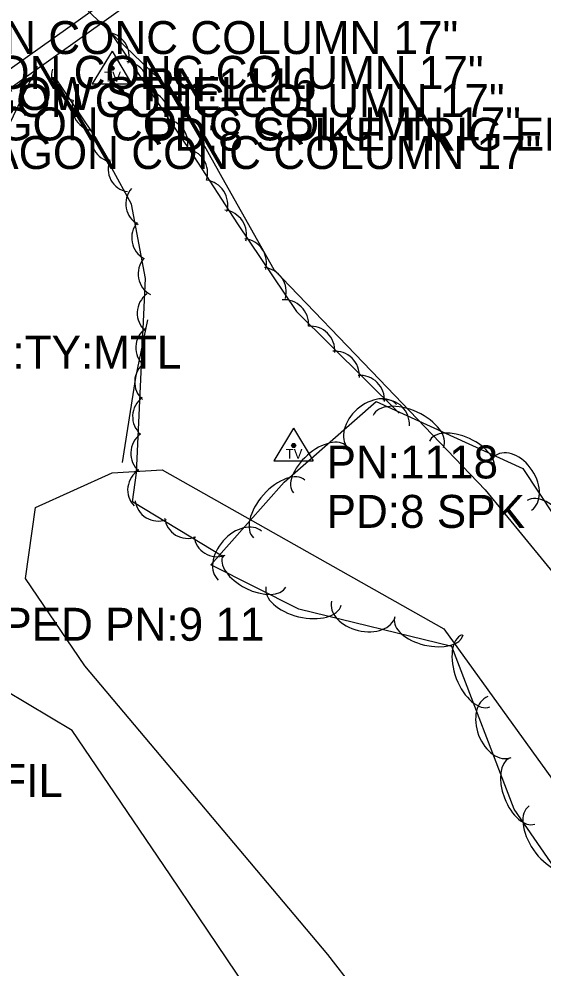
# Model space of a CAD drawing. Extents: x 1451369 to 1458940, y 1868647 to 1875095.
# Drawn here: x 1454278.5 to 1454358, y 1871314.6 to 1871458.6 of the extents above; entities that cross this region are included whole.
import ezdxf

# ---------------------------------------------------------------- set-up
doc = ezdxf.new("R2010")
doc.units = 0
for name, color, linetype in [('E_Existing_ROW', 7, 'Continuous'), ('E_Quarter Section Line', 7, 'Continuous'), ('E_ROW Point Number', 7, 'Continuous'), ('E_Station Offset', 7, 'Continuous'), ('E_Tract Residual', 7, 'Continuous'), ('S_EXIST_ROW', 7, 'Continuous'), ('S_MISC_BOUNDARY', 7, 'Continuous'), ('S_MISC_STRUCTURES_ANNOT', 7, 'Continuous'), ('S_PARKING', 7, 'Continuous'), ('S_PRIMARY_CTL_ANNOT', 7, 'Continuous'), ('S_SECONDARY_CTL_ANNOT', 7, 'Continuous'), ('S_SIDE_DRAIN_ANNOT', 7, 'Continuous'), ('S_SURVEY_TEXT_ANNOT', 7, 'Continuous')]:
    doc.layers.add(name, color=color, linetype=linetype)

msp = doc.modelspace()

# ---------------------------------------------------------------- linework, layer by layer
at = {"layer": 'E_Existing_ROW'}
msp.add_line((1454227.64, 1871415.7), (1454553.13, 1871647.85), dxfattribs=at)
at = {"layer": 'E_Quarter Section Line'}
msp.add_line((1454551.64, 1871643.91), (1454234.22, 1871417.39), dxfattribs=at)
at = {"layer": 'E_ROW Point Number'}
for points in [[(1454292.27, 1871456.79), (1454305.07, 1871437.72), (1454311.68, 1871427.52), (1454320.66, 1871414.23), (1454336.23, 1871398.78)], [(1454309.62, 1871376.9), (1454295.77, 1871385.31), (1454296.35, 1871389.74), (1454297.71, 1871419.2), (1454295.61, 1871430.5), (1454289.64, 1871441.43), (1454283.98, 1871449.8)], [(1454377.48, 1871304.11), (1454353.64, 1871338.7), (1454344.21, 1871363.37), (1454320.99, 1871369.01), (1454307.64, 1871375.76), (1454318.78, 1871388.29), (1454332.74, 1871400.56), (1454354.98, 1871390.38), (1454371.8, 1871364.92)]]:
    msp.add_lwpolyline(points, dxfattribs=at)
for centre, major_axis, ratio, start_param, end_param in [((1454291.71, 1871453.01), (-2.03, 3.02), 0.965975, 3.824523, 5.597723), ((1454294.63, 1871448.55), (-2.03, 3.02), 0.965975, 3.824523, 5.597723), ((1454287.1, 1871449.93), (2.04, -3.02), 0.99929, 3.825789, 5.598989), ((1454297.63, 1871444.2), (-2.03, 3.02), 0.965975, 3.824523, 5.597723), ((1454290.24, 1871445.23), (2.04, -3.02), 0.99929, 3.825789, 5.598989), ((1454300.61, 1871439.82), (-2.03, 3.02), 0.965975, 3.824523, 5.597723), ((1454293.15, 1871440.47), (-2.69, -2.46), 0.973191, 5.162702, 6.935903), ((1454303.6, 1871435.32), (-1.98, 3.06), 0.965979, 3.825789, 5.598989), ((1454295.66, 1871435.95), (-2.69, -2.46), 0.973191, 5.162702, 6.935903), ((1454306.65, 1871430.56), (-1.98, 3.06), 0.965979, 3.825789, 5.598989), ((1454298.35, 1871430.63), (-2.7, -2.45), 0.978082, 4.853565, 6.626766), ((1454309.52, 1871426), (-2.02, 3.03), 0.965974, 3.833043, 5.606243), ((1454299.24, 1871425.46), (-2.7, -2.45), 0.978082, 4.853565, 6.626766), ((1454312.54, 1871421.67), (-2.02, 3.03), 0.965974, 3.833043, 5.606243), ((1454300.22, 1871419.99), (-2.7, -2.45), 0.978082, 4.853565, 6.626766), ((1454315.53, 1871417.29), (-2.02, 3.03), 0.965974, 3.833043, 5.606243), ((1454300.08, 1871414.03), (-2.78, -2.36), 0.977897, 4.656834, 6.430034), ((1454318.92, 1871412.38), (-2.02, 3.03), 0.965974, 4.035108, 5.808309), ((1454299.87, 1871408.79), (-2.78, -2.36), 0.977897, 4.656834, 6.430034), ((1454322.9, 1871408.38), (-2.02, 3.03), 0.965974, 4.035108, 5.808309), ((1454326.63, 1871404.58), (-2.02, 3.03), 0.965974, 4.035108, 5.808309), ((1454299.7, 1871403.58), (-2.78, -2.36), 0.977897, 4.656834, 6.430034), ((1454330.43, 1871400.91), (-2.02, 3.03), 0.965974, 4.035108, 5.808309), ((1454299.39, 1871398.32), (-2.78, -2.36), 0.977897, 4.656834, 6.430034), ((1454332.1, 1871396.82), (-3.72, -3.27), 0.68531, 3.141593, 6.283185), ((1454337.6, 1871396), (-5.34, 2.44), 0.549965, 3.141593, 6.283185), ((1454334.21, 1871397.21), (-2.02, 3.03), 0.965974, 4.035108, 5.808309), ((1454299.1, 1871392.74), (-2.78, -2.36), 0.977897, 4.656834, 6.430034), ((1454345.66, 1871392.31), (-4.86, 2.23), 0.540586, 3.141593, 6.283185), ((1454324.19, 1871390.22), (-4.02, -3.53), 0.540698, 3.141593, 6.283185), ((1454353.56, 1871388.21), (-2.73, 4.14), 0.685157, 3.141593, 6.283185), ((1454298.64, 1871387.23), (-3.23, -1.69), 0.963479, 4.801554, 6.574754), ((1454318.02, 1871384.24), (-3.9, -4.38), 0.550079, 3.141593, 6.283185), ((1454299.74, 1871386.01), (2.57, 2.58), 0.981285, 2.488192, 4.261392), ((1454358.88, 1871380.63), (-3.23, 4.9), 0.549956, 3.141593, 6.283185), ((1454304.21, 1871383.38), (2.57, 2.58), 0.981285, 2.488192, 4.261392), ((1454312.06, 1871377.15), (-3.29, -3.7), 0.68531, 3.141593, 6.283185), ((1454308.65, 1871380.6), (2.57, 2.58), 0.981285, 2.488192, 4.261392), ((1454314.24, 1871374.8), (4.77, -2.41), 0.540583, 3.141593, 6.283185), ((1454321.71, 1871371.02), (5.7, -1.38), 0.549983, 3.141593, 6.283185), ((1454330.77, 1871369.09), (4.82, -1.17), 0.685191, 3.141593, 6.283185), ((1454340.72, 1871366.4), (5.2, -1.26), 0.540605, 3.141593, 6.283185), ((1454347.89, 1871359.68), (2.1, -5.48), 0.549973, 3.141593, 6.283185), ((1454351.44, 1871351.13), (1.77, -4.63), 0.685178, 3.141593, 6.283185), ((1454354.88, 1871341.41), (1.91, -4.99), 0.540595, 3.141593, 6.283185), ((1454359.24, 1871334.33), (3.33, -4.83), 0.549955, 3.141593, 6.283185)]:
    msp.add_ellipse(centre, major_axis=major_axis, ratio=ratio, start_param=start_param, end_param=end_param, dxfattribs=at)
at = {"layer": 'E_Station Offset'}
for p, q in [((1454292.65, 1871453.73), (1454289.64, 1871448.78)), ((1454292.65, 1871453.73), (1454295.6, 1871448.78)), ((1454289.64, 1871448.78), (1454295.6, 1871448.78)), ((1454320.2, 1871396.49), (1454317.19, 1871391.53)), ((1454320.2, 1871396.49), (1454323.15, 1871391.53)), ((1454317.19, 1871391.53), (1454323.15, 1871391.53))]:
    msp.add_line(p, q, dxfattribs=at)
for centre, radius in [((1454292.65, 1871451.12), 0.311), ((1454292.65, 1871451.12), 0.183), ((1454292.65, 1871451.12), 0.103), ((1454320.2, 1871393.87), 0.311), ((1454320.2, 1871393.87), 0.183), ((1454320.2, 1871393.87), 0.103)]:
    msp.add_circle(centre, radius, dxfattribs=at)
at = {"layer": 'E_Tract Residual'}
msp.add_lwpolyline([(1454284.21, 1871464.5), (1454293.3, 1871455.74), (1454302.39, 1871446.97), (1454309.79, 1871433.77), (1454317.19, 1871420.58), (1454333.21, 1871403.87), (1454349.24, 1871387.16), (1454364.16, 1871368.92), (1454379.07, 1871350.69), (1454393.99, 1871332.45), (1454408.91, 1871314.21), (1454419.51, 1871302.02), (1454430.1, 1871289.83), (1454440.7, 1871277.65), (1454451.3, 1871265.46), (1454464.12, 1871251.23), (1454476.93, 1871237), (1454489.75, 1871222.77), (1454502.57, 1871208.55), (1454514.12, 1871195.2), (1454525.67, 1871181.84), (1454537.22, 1871168.49), (1454548.77, 1871155.14)], dxfattribs=at)
at = {"layer": 'S_EXIST_ROW'}
for points in [[(1454201.55, 1871360.21), (1454219.09, 1871372.04), (1454227.97, 1871377.68), (1454230.98, 1871381.48), (1454247.58, 1871392.86), (1454258.52, 1871408.84), (1454259.95, 1871417.16), (1454273.24, 1871434.8), (1454281.33, 1871451.46)], [(1454294.23, 1871391.31), (1454296.25, 1871404.17), (1454298.06, 1871412.94)]]:
    msp.add_lwpolyline(points, dxfattribs=at)
at = {"layer": 'S_MISC_BOUNDARY'}
msp.add_lwpolyline([(1454508.04, 1871132.59), (1454480.07, 1871123.31), (1454450.16, 1871133.48), (1454419.11, 1871179.34), (1454386.64, 1871235.64), (1454345.34, 1871290.82), (1454325.41, 1871316.62), (1454288.53, 1871360.43), (1454279.55, 1871373.71), (1454281.02, 1871384.44), (1454292.69, 1871389.73), (1454300.28, 1871390.19), (1454342.99, 1871366.06), (1454378.58, 1871316.67), (1454411.72, 1871280.3)], dxfattribs=at)
at = {"layer": 'S_PARKING'}
msp.add_lwpolyline([(1454175.25, 1871357.91), (1454187.26, 1871346.22), (1454208.3, 1871338.38), (1454223.66, 1871323.05), (1454242.1, 1871308.07), (1454266.52, 1871302.24), (1454282.9, 1871301.24), (1454315.4, 1871284.76), (1454323.88, 1871297.21), (1454314.37, 1871309.59), (1454301.45, 1871328.71), (1454286.62, 1871350.64), (1454269.62, 1871360.74), (1454257.03, 1871361.79), (1454244.36, 1871358.02), (1454223, 1871351.82), (1454213.28, 1871352.13), (1454198.42, 1871356.78), (1454186.28, 1871370.97)], dxfattribs=at)

# ---------------------------------------------------------------- texts
at = {"layer": 'E_Station Offset'}
for p in [(1454291.45, 1871449.11), (1454318.99, 1871391.86)]:
    msp.add_text('TV', height=1.5, rotation=360, dxfattribs=at).set_placement(p)
at = {"layer": 'S_MISC_STRUCTURES_ANNOT'}
for s, p in [('OCTAGON CONC COLUMN 17"', (1454247.32, 1871453.28)), ('OCTAGON CONC COLUMN 17"', (1454251.17, 1871448)), ('OCTAGON CONC COLUMN 17"', (1454254.36, 1871443.73)), ('LOW STEEL', (1454274.59, 1871444.79)), ('OCTAGON CONC COLUMN 17"', (1454256.83, 1871440.17)), ('OCTAGON CONC COLUMN 17"', (1454259.91, 1871435.83))]:
    msp.add_text(s, height=5, dxfattribs=at).set_placement(p)
at = {"layer": 'S_PRIMARY_CTL_ANNOT'}
msp.add_text('PD:STD AHTD MON STAMPED PN:9 11', height=5, dxfattribs=at).set_placement((1454193.54, 1871364.24))
at = {"layer": 'S_SECONDARY_CTL_ANNOT'}
for s, p in [('PN:1116', (1454297.65, 1871446.12)), ('PD:8 SPIKE TRIG ELEV', (1454297.65, 1871438.62)), ('PN:1118', (1454325.2, 1871388.87)), ('PD:8 SPK', (1454325.2, 1871381.37))]:
    msp.add_text(s, height=5, dxfattribs=at).set_placement(p)
at = {"layer": 'S_SIDE_DRAIN_ANNOT'}
msp.add_text('DI:24" TY:RCP LN:29\' CN:15% FIL', height=5, dxfattribs=at).set_placement((1454181.23, 1871340.52))
at = {"layer": 'S_SURVEY_TEXT_ANNOT'}
msp.add_text('GD Y:MTL GD PD:TY:MTL', height=5, dxfattribs=at).set_placement((1454222.93, 1871405.53))

doc.saveas('drawing.dxf')
